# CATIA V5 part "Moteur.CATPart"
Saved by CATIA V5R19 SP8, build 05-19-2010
Part number: Moteur
Bounding box of the stored display mesh (mm): x -23.5 to -0.5, y -25 to -13.5, z -11.5 to 11.5
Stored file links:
  G:\EU_thinkMotion\CFAO_2010\MMS_groupe3\MMS_groupe3\jbonnamy\jbonnamy_cfao\Moteur.CATPart
  G:\EU_thinkMotion\CFAO_2010\MMS_groupe3\MMS_groupe3\jbonnamy\jbonnamy_cfao\jbonnamy_suspension.arriere.directionnelle.CATProduct
  G:\EU_thinkMotion\CFAO_2010\MMS_groupe3\MMS_groupe3\jbonnamy\jbonnamy_cfao\Bras.1.CATPart
  G:\EU_thinkMotion\CFAO_2010\MMS_groupe3\MMS_groupe3\jbonnamy\jbonnamy_cfao\SKL.general.CATPart
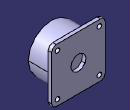
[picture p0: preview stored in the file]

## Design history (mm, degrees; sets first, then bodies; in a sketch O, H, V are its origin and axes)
Parameters
  LENGTH = 18 mm
  LENGTH = 6 mm
  LENGTH = 2 mm
  LENGTH = 6.5 mm
  LENGTH = 1.5 mm
  LENGTH = 18 mm
  LENGTH = 6 mm
  LENGTH = 2 mm
  LENGTH = 6.5 mm
External parameters (linked from other documents)
  External.Largeur.et.hauteur.plaque.moteur = 23 mm
  External.Epaisseur.support.10 = 1.5 mm
  `External.Rayon.congé.plaque.moteur` = 2 mm
  External.Diametre.vis.sans.fin = 6.5 mm
  External.Diametre.vis.fixation = 2 mm
  External.Diametre.primitif.roue = 18 mm
  External.Diametre.primitif.vis.sans.fin = 6 mm
  External.Diametre.moteur = 20 mm
Set1
  Plane1: linked copy from another document
  Point1 "Point.vis.sans.fin": linked copy from another document
Body1 (main body)
  Sketch1 on Plane1, origin (0, -13.5, 0), H (-1, 0, 0), V (0, 0, 1)
    line L1 (21.5, 11.5) -> (2.5, 11.5)
    line L2 (0.5, 9.5) -> (0.5, -9.5)
    line L3 (2.5, -11.5) -> (21.5, -11.5)
    line L4 (23.5, -9.5) -> (23.5, 9.5)
    reference projected point E1 (12, 0) from Point1
    reference projected point E2 (12, 0) from Point1
    arc A1 centre (2.5, 9.5) radius 2 from (2.5, 11.5) to (0.5, 9.5) ccw
    point P3 (2.5, 9.5)
    arc A2 centre (21.5, 9.5) radius 2 from (21.5, 11.5) to (23.5, 9.5) cw
    point P6 (21.5, 9.5)
    arc A3 centre (2.5, -9.5) radius 2 from (0.5, -9.5) to (2.5, -11.5) ccw
    point P9 (2.5, -9.5)
    arc A4 centre (21.5, -9.5) radius 2 from (21.5, -11.5) to (23.5, -9.5) ccw
    point P12 (21.5, -9.5)
    distance L2 L4 = 23 {= External.Largeur.et.hauteur.plaque.moteur}
    distance L1 L3 = 23 {= External.Largeur.et.hauteur.plaque.moteur}
    distance L2 E1 = 11.5 {= External.Largeur.et.hauteur.plaque.moteur /2}
    distance L1 E2 = 11.5 {= External.Largeur.et.hauteur.plaque.moteur /2}
    radius A1 = 2 {= `External.Rayon.congé.plaque.moteur`}
    distance P3 L1 = 2 {= `External.Rayon.congé.plaque.moteur`}
    distance P3 L2 = 2 {= `External.Rayon.congé.plaque.moteur`}
    radius A2 = 2 {= `External.Rayon.congé.plaque.moteur`}
    distance P6 L4 = 2 {= `External.Rayon.congé.plaque.moteur`}
    distance P6 L1 = 2 {= `External.Rayon.congé.plaque.moteur`}
    radius A3 = 2 {= `External.Rayon.congé.plaque.moteur`}
    distance P9 L2 = 2 {= `External.Rayon.congé.plaque.moteur`}
    distance P9 L3 = 2 {= `External.Rayon.congé.plaque.moteur`}
    radius A4 = 2 {= `External.Rayon.congé.plaque.moteur`}
    distance P12 L4 = 2 {= `External.Rayon.congé.plaque.moteur`}
    distance P12 L3 = 2 {= `External.Rayon.congé.plaque.moteur`}
  Pad1: profile Sketch1, direction (0, -1, 0), length 1.5 {= External.Epaisseur.support.10}
  Sketch2 on end face of Pad1, origin (0, -15, 0), H (-1, 0, 0), V (0, 0, 1)
    point P1 (12, 0)
    reference projected point E1 (12, 0) from Point1
    circle A1 centre (21, 9) radius 1
    point P2 (21, 9)
    circle A2 centre (3, 9) radius 1
    point P3 (3, 9)
    circle A3 centre (21, -9) radius 1
    point P4 (21, -9)
    circle A4 centre (3, -9) radius 1
    point P5 (3, -9)
    distance P1 E1 = 0
    radius A1 = 1 {= External.Diametre.vis.fixation /2}
    radius A2 = 1 {= External.Diametre.vis.fixation /2}
    radius A4 = 1 {= External.Diametre.vis.fixation /2}
    radius A3 = 1 {= External.Diametre.vis.fixation /2}
    distance P3 H = 9
    distance P2 H = 9
    distance P5 H = 9
    distance P4 H = 9
    distance P3 V = 3 {= (External.Diametre.primitif.roue +External.Diametre.primitif.vis.sans.fin )/2-9mm}
    distance P2 V = 21 {= (External.Diametre.primitif.roue  +External.Diametre.primitif.vis.sans.fin  )/2+9mm}
    distance P5 V = 3 {= (External.Diametre.primitif.roue +External.Diametre.primitif.vis.sans.fin )/2-9mm}
    distance P4 V = 21 {= (External.Diametre.primitif.roue +External.Diametre.primitif.vis.sans.fin )/2+9mm}
  Pocket1: profile Sketch2, direction (0, 1, 0), length 1.5 {= External.Epaisseur.support.10}
  Sketch3 on end face of Pad1, origin (0, -15, 0), H (1, 0, 0), V (0, 0, 1)
    circle A1 centre (-12, 0) radius 10
    point P1 (-12, 0)
    reference projected point E1 (-12, 0) from Point1
    radius A1 = 10 {= External.Diametre.moteur /2}
    distance P1 E1 = 0
  Pad2: profile Sketch3, direction (0, -1, 0), length 10
  Sketch4 on Plane1, origin (0, -13.5, 0), H (1, 0, 0), V (0, 0, -1)
    point P1 (-12, 0)
    reference projected point E1 (-12, 0) from Point1
    distance P1 E1 = 0
  Hole1: placed by Sketch4, at (-12, -13.5, 0) direction (0, -1, 0), diameter 6.5 {= External.Diametre.vis.sans.fin}, depth 1.5 {= External.Epaisseur.support.10}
